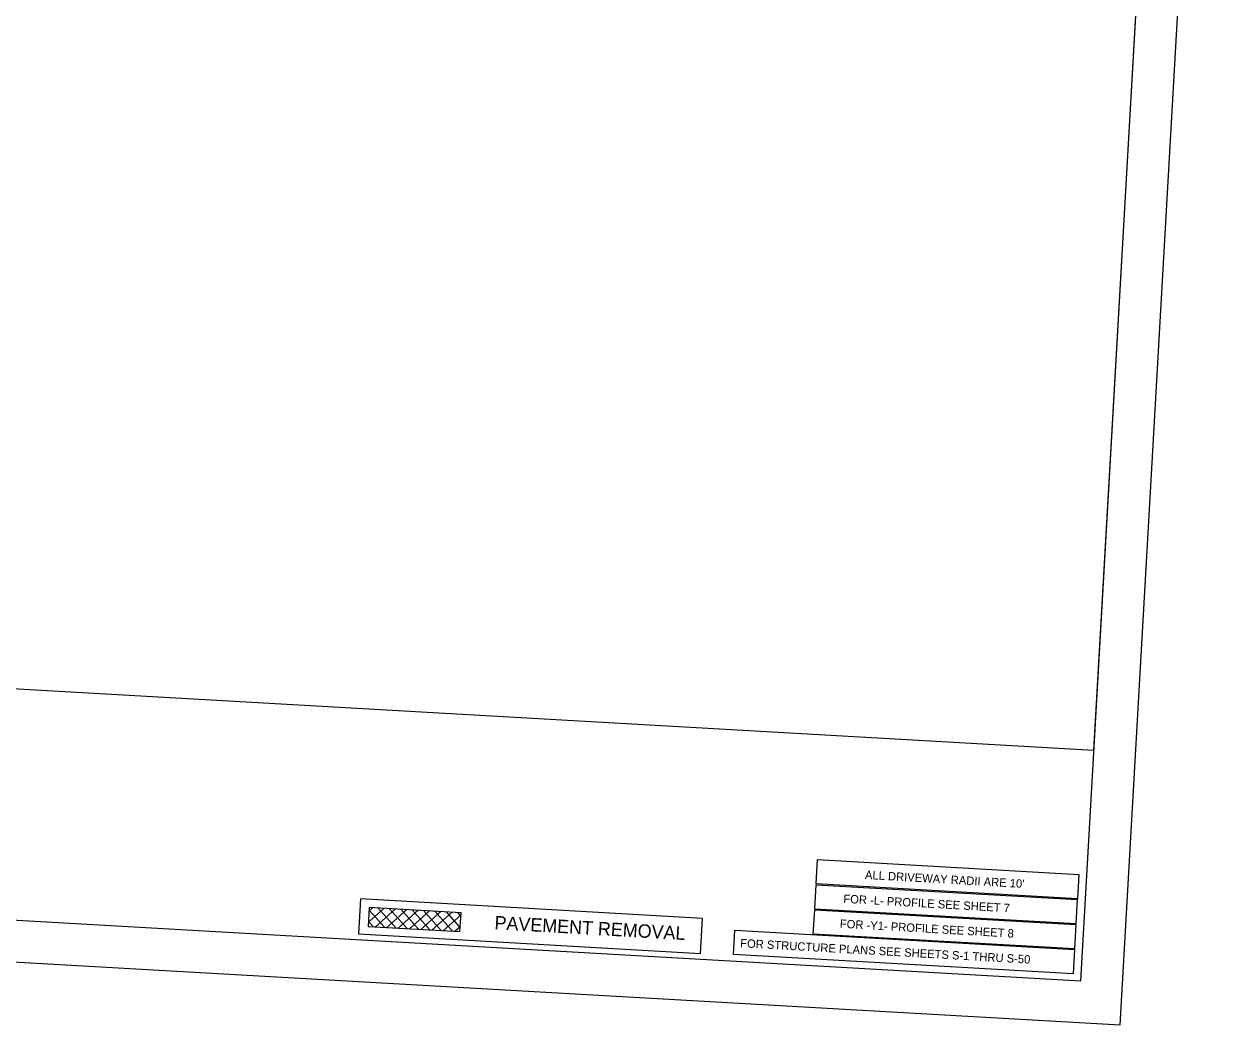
# Model space of a CAD drawing. Extents: x 2604316 to 2606605, y 617090 to 619543.
# Drawn here: x 2605358 to 2606075, y 617913 to 618510 of the extents above; entities that cross this region are included whole.
import ezdxf

# ---------------------------------------------------------------- set-up
doc = ezdxf.new("R2010")
doc.units = 0
for name, color, linetype in [('Prop DSN Text', 7, 'Continuous'), ('Prop Grid Mask', 7, 'Continuous'), ('Prop Horizontal Alignment Station Label', 7, 'Continuous'), ('Prop Rem of Exist Asph Pvmt', 7, 'Continuous'), ('Scratch_Level_1', 7, 'Continuous'), ('Sheet Plan And Profile CELL', 7, 'Continuous'), ('Stewart Plot Border Xerox6279 and LJ5000', 7, 'Continuous')]:
    doc.layers.add(name, color=color, linetype=linetype)

msp = doc.modelspace()

# ---------------------------------------------------------------- linework, layer by layer
at = {"layer": 'Prop Grid Mask'}
for points in [[(2605557.96, 617966.87), (2605762.26, 617955.23), (2605763.45, 617976.11), (2605559.15, 617987.75)], [(2605619.26, 617979.49), (2605564.45, 617982.61), (2605563.81, 617971.37), (2605618.62, 617968.25)]]:
    msp.add_lwpolyline(points, close=True, dxfattribs=at)
at = {"layer": 'Prop Horizontal Alignment Station Label'}
for points in [[(2605987.3, 617987.78), (2605831.33, 617996.66), (2605832.15, 618011.18), (2605988.13, 618002.3)], [(2605986.45, 617972.83), (2605830.47, 617981.71), (2605831.3, 617996.23), (2605987.28, 617987.35)], [(2605985.6, 617957.88), (2605829.62, 617966.76), (2605830.45, 617981.28), (2605986.43, 617972.4)], [(2605984.75, 617942.93), (2605781.94, 617954.48), (2605782.77, 617969), (2605985.58, 617957.45)]]:
    msp.add_lwpolyline(points, close=True, dxfattribs=at)
at = {"layer": 'Prop Rem of Exist Asph Pvmt'}
for p, q in [((2605563.95, 617973.8), (2605573.26, 617982.11)), ((2605564.33, 617980.58), (2605566.48, 617982.5)), ((2605564.36, 617981.05), (2605573.49, 617970.82)), ((2605568.16, 617971.12), (2605580.04, 617981.73)), ((2605569.66, 617982.32), (2605580.27, 617970.43)), ((2605574.93, 617970.74), (2605586.82, 617981.34)), ((2605576.44, 617981.93), (2605587.04, 617970.05)), ((2605581.71, 617970.35), (2605593.6, 617980.95)), ((2605583.22, 617981.54), (2605593.82, 617969.66)), ((2605588.49, 617969.97), (2605600.37, 617980.57)), ((2605590, 617981.16), (2605600.6, 617969.28)), ((2605595.27, 617969.58), (2605607.15, 617980.18)), ((2605596.78, 617980.77), (2605607.38, 617968.89)), ((2605602.05, 617969.19), (2605613.93, 617979.8)), ((2605603.55, 617980.39), (2605614.16, 617968.5)), ((2605608.82, 617968.81), (2605619.18, 617978.05)), ((2605610.33, 617980), (2605618.75, 617970.56)), ((2605617.11, 617979.61), (2605619.14, 617977.34)), ((2605563.97, 617974.27), (2605566.71, 617971.21)), ((2605615.6, 617968.42), (2605618.8, 617971.27))]:
    msp.add_line(p, q, dxfattribs=at)
at = {"layer": 'Scratch_Level_1'}
msp.add_lwpolyline([(2606037.66, 618786.46), (2605837.94, 618797.83), (2605849.36, 618998.56), (2604589.3, 619070.32), (2604537.44, 618159.71), (2605997.22, 618076.57)], close=True, dxfattribs=at)
msp.add_lwpolyline([(2606037.66, 618786.46), (2605837.94, 618797.83), (2605849.36, 618998.56), (2604589.3, 619070.32), (2604537.44, 618159.71), (2605997.22, 618076.57)], close=True, dxfattribs=at)
at = {"layer": 'Sheet Plan And Profile CELL'}
msp.add_lwpolyline([(2606049.09, 618987.18), (2604551.51, 619072.48), (2604491.81, 618024.18), (2605989.38, 617938.88)], close=True, dxfattribs=at)
at = {"layer": 'Stewart Plot Border Xerox6279 and LJ5000'}
msp.add_lwpolyline([(2604315.67, 618009.17), (2606012.92, 617912.5), (2606075.47, 619010.72), (2604378.22, 619107.39)], close=True, dxfattribs=at)

# ---------------------------------------------------------------- texts
at = {"layer": 'Prop DSN Text'}
msp.add_text('PAVEMENT REMOVAL', height=8, rotation=356.74026, dxfattribs=at).set_placement((2605639.09, 617969.66))
at = {"layer": 'Prop Horizontal Alignment Station Label'}
for s, p in [("ALL DRIVEWAY RADII ARE 10'", (2605860.39, 617999.69)), ('FOR -L- PROFILE SEE SHEET 7', (2605847.46, 617985.42)), ('FOR -Y1- PROFILE SEE SHEET 8', (2605845.37, 617970.54)), ('FOR STRUCTURE PLANS SEE SHEETS S-1 THRU S-50', (2605785.85, 617958.94))]:
    msp.add_text(s, height=5, rotation=356.74026, dxfattribs=at).set_placement(p)

doc.saveas('drawing.dxf')
